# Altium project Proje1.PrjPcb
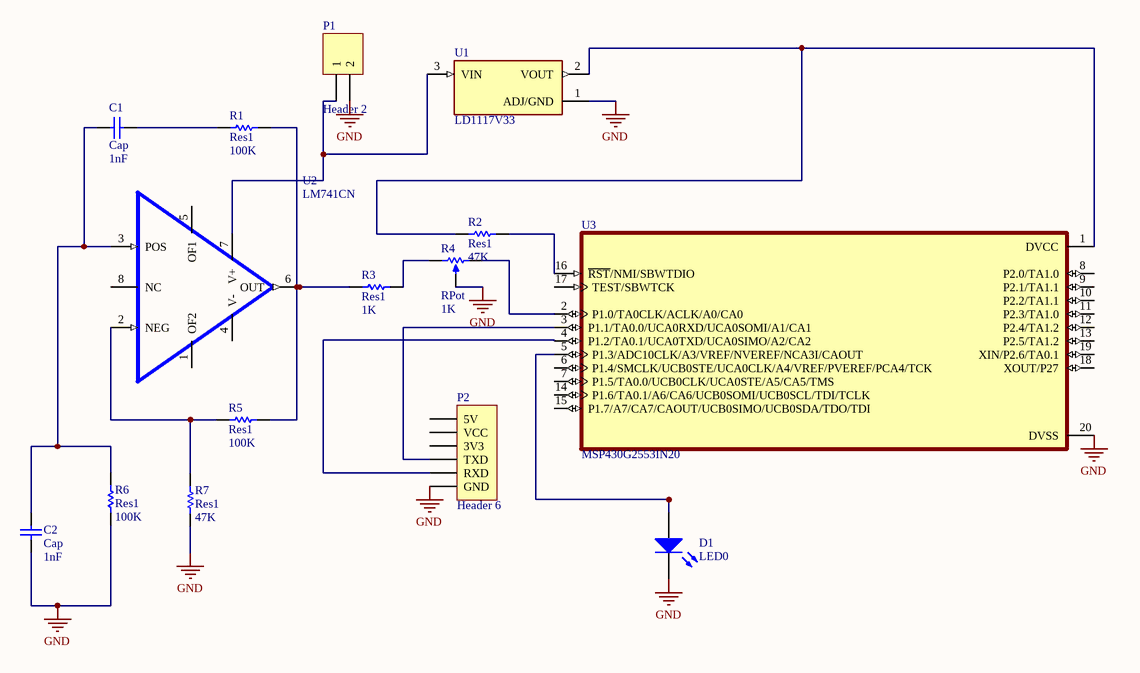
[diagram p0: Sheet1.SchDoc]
1 sheet, 15 parts. Net scope: global (net labels, ports and power ports of the same name join across sheets).
Board file: cizim1.PcbDoc

## Sheet Sheet1.SchDoc
size A4; SheetNumber: 1; SheetTotal: 1

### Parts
C1  Cap  value 1nF  [RAD-0.3]
C2  Cap  value 1nF  [RAD-0.3]
D1  LED0  [LED-0]
P1  Header 2  [HDR1X2]
P2  Header 6  [HDR1X6]
R1  Res1  value 100K  [AXIAL-0.3]
R2  Res1  value 47K  [AXIAL-0.3]
R3  Res1  value 1K  [AXIAL-0.3]
R4  RPot  value 1K  [VR5]
R5  Res1  value 100K  [AXIAL-0.3]
R6  Res1  value 100K  [AXIAL-0.3]
R7  Res1  value 47K  [AXIAL-0.3]
U1  LD1117V33  [TO255P1020X450X1968-3]
U2  LM741CN  [DIP254P762X508-8]
U3  MSP430G2553IN20  [DIP794W45P254L2692H508Q20]

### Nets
GND: C2.2 D1.2(K) P1.2 P2.6(GND) R4.3(TAP) R6.1 R7.2 U1.1(ADJ/GND) U3.20(DVSS)
NetC1_1: C1.1 R1.1
NetC1_2: C1.2 C2.1 R6.2 U2.3(POS)
NetD1_1: D1.1(A) U3.5(P1.3/ADC10CLK/A3/VREF/NVEREF/NCA3I/CAOUT)
NetP1_1: P1.1 U1.3(VIN) U2.7(V+)
NetP2_4: P2.4(TXD) U3.3(P1.1/TA0.0/UCA0RXD/UCA0SOMI/A1/CA1)
NetP2_5: P2.5(RXD) U3.4(P1.2/TA0.1/UCA0TXD/UCA0SIMO/A2/CA2)
NetR1_2: R1.2 R3.2 R5.1 U2.6(OUT)
NetR2_1: R2.1 U3.16(~{RST}/NMI/SBWTDIO)
NetR2_2: R2.2 U1.2(VOUT) U3.1(DVCC)
NetR3_1: R3.1 R4.1(TOP)
NetR4_2: R4.2(BOT) U3.2(P1.0/TA0CLK/ACLK/A0/CA0)
NetR5_2: R5.2 R7.1 U2.2(NEG)

Not connected (* = marked no-connect by the designer): P2 1(5V) 2(VCC) 3(3V3); U2 1(OF2) 4(V-) 5(OF1) 8(NC); U3 6(P1.4/SMCLK/UCB0STE/UCA0CLK/A4/VREF/PVEREF/PCA4/TCK) 7(P1.5/TA0.0/UCB0CLK/UCA0STE/A5/CA5/TMS) 8(P2.0/TA1.0) 9(P2.1/TA1.1) 10(P2.2/TA1.1) 11(P2.3/TA1.0) 12(P2.4/TA1.2) 13(P2.5/TA1.2) 14(P1.6/TA0.1/A6/CA6/UCB0SOMI/UCB0SCL/TDI/TCLK) 15(P1.7/A7/CA7/CAOUT/UCB0SIMO/UCB0SDA/TDO/TDI) 17(TEST/SBWTCK) 18(XOUT/P27) 19(XIN/P2.6/TA0.1)

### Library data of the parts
C1 C2 = Cap: Capacitor
D1 = LED0: Typical INFRARED GaAs LED
P1 = Header 2: Header, 2-Pin
P2 = Header 6: Header, 6-Pin
R1-R3 R5-R7 = Res1: Resistor
R4 = RPot: Potentiometer; Sim Note: Enter the Resistance value and the set point into parameter fields.; Set Position: 0.5
U1 = LD1117V33: Linear Voltage Regulator IC Positive Fixed 1 Output 800mA TO-220AB; MF: STMicroelectronics
U2 = LM741CN: General Purpose Amplifier 1 Circuit 8-DIP; MF: ON Semiconductor
U3 = MSP430G2553IN20: MSP430G2x53, MSP430G2x13 Mixed Signal Microcontroller 20-PDIP -40 to 85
